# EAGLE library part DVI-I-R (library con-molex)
CONNECTOR MiroCross(TM)-DVI i/0 plug and receptacle connector system (scart)
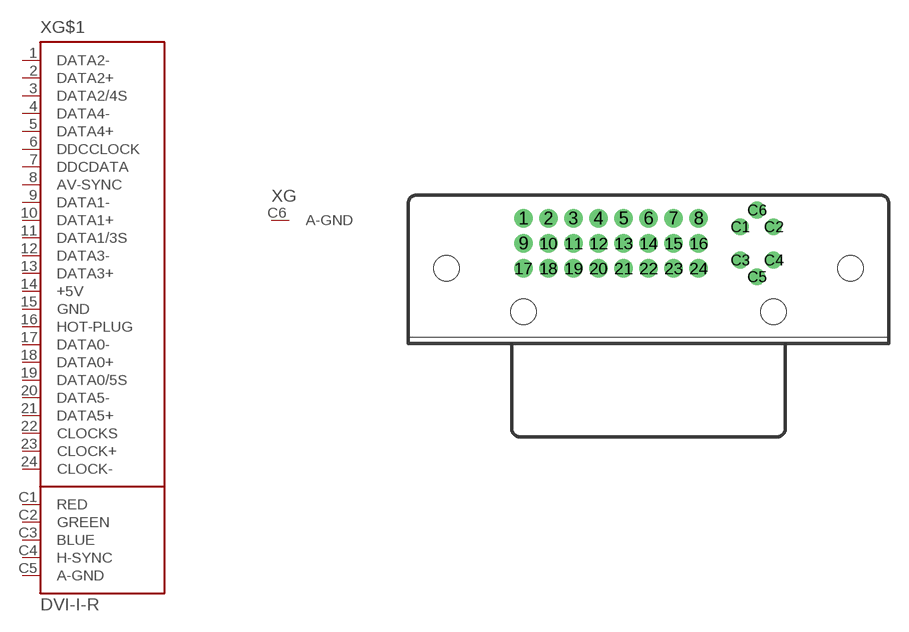
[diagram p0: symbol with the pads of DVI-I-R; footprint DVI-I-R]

Designator prefix X; gates G$1=DVI-I G=AGND

## DVI-I-R (OC_FARNELL: unknown; OC_NEWARK: unknown)  [DVI-I-R]
1  G$1:DATA2-  pas
2  G$1:DATA2+  pas
3  G$1:DATA2/4S  pas
4  G$1:DATA4-  pas
5  G$1:DATA4+  pas
6  G$1:DDCCLOCK  pas
7  G$1:DDCDATA  pas
8  G$1:AV-SYNC  pas
9  G$1:DATA1-  pas
10  G$1:DATA1+  pas
11  G$1:DATA1/3S  pas
12  G$1:DATA3-  pas
13  G$1:DATA3+  pas
14  G$1:+5V  pwr
15  G$1:GND  pwr
16  G$1:HOT-PLUG  pas
17  G$1:DATA0-  pas
18  G$1:DATA0+  pas
19  G$1:DATA0/5S  pas
20  G$1:DATA5-  pas
21  G$1:DATA5+  pas
22  G$1:CLOCKS  pas
23  G$1:CLOCK+  pas
24  G$1:CLOCK-  pas
C1  G$1:RED  pas
C2  G$1:GREEN  pas
C3  G$1:BLUE  pas
C4  G$1:H-SYNC  pas
C5  G$1:A-GND  pwr
C6  G:A-GND  pwr

## Footprint DVI-I-R (pad centres in mm)
CONNECTOR MiroCross(TM)-DVI i/0 plug and receptacle connector system (scart)
drill 0.864 pad 1.397 round: 1 -9.525,6.985; 2 -7.62,6.985; 3 -5.715,6.985; 4 -3.81,6.985; 5 -1.905,6.985; 6 0,6.985; 7 1.905,6.985; 8 3.81,6.985; 9 -9.525,5.08; 10 -7.62,5.08; 11 -5.715,5.08; 12 -3.81,5.08; 13 -1.905,5.08; 14 0,5.08; 15 1.905,5.08; 16 3.81,5.08; 17 -9.525,3.175; 18 -7.62,3.175; 19 -5.715,3.175; 20 -3.81,3.175; 21 -1.905,3.175; 22 0,3.175; 23 1.905,3.175; 24 3.81,3.175
drill 0.66 pad 1.27 round: C1 6.985,6.35; C2 9.525,6.35; C3 6.985,3.81; C4 9.525,3.81; C5 8.255,2.54; C6 8.255,7.62
hole 1.93 at -15.367,3.175
hole 1.93 at 15.367,3.175
hole 1.93 at -9.525,-0.127
hole 1.93 at 9.525,-0.127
